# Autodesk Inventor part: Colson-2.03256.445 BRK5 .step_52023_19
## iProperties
Created: 2010-10
Part Number: Colson-2.03256.445 BRK5 .step_52023_19
Document SubType Name: Modeling
Designer: Administrator
Density: 7.85 g/cm^3
Material: Steel
Mass: 73.1668 g
Surface Area: 132.974 cm^2
Volume: 9.32061 cm^3
Author: Administrator
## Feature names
1. Base1
